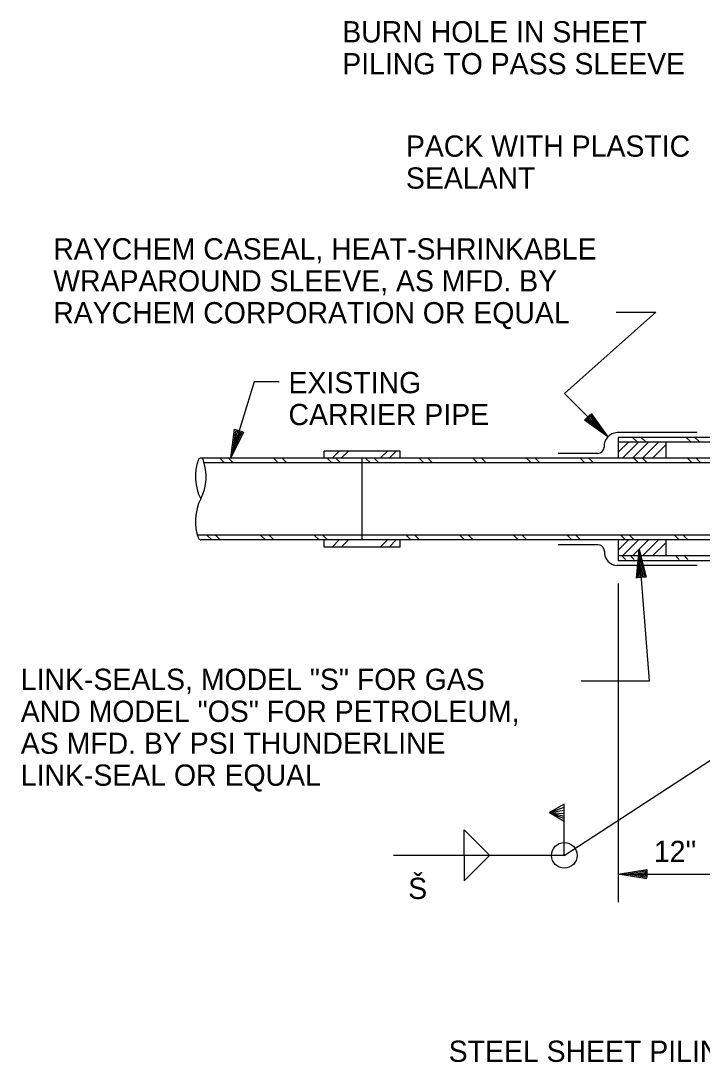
# Model space of a CAD drawing. Extents: x 22422.9 to 22498.9, y 22369.6 to 22415.
# Drawn here: x 22422.88 to 22428.87, y 22387.54 to 22396.69 of the extents above; entities that cross this region are included whole.
import ezdxf

# ---------------------------------------------------------------- set-up
doc = ezdxf.new("R2010")
doc.units = 0
for name, color, linetype in [('Level 1', 7, 'Continuous'), ('Level 10', 7, 'Continuous'), ('Level 2', 7, 'Continuous'), ('Level 4', 7, 'Continuous'), ('Level 7', 7, 'Continuous'), ('Level 8', 7, 'Continuous')]:
    doc.layers.add(name, color=color, linetype=linetype)

msp = doc.modelspace()

# ---------------------------------------------------------------- linework, layer by layer
at = {"layer": 'Level 1'}
for p, q in [((22431.1304, 22393.029), (22428.1304, 22393.029)), ((22431.1304, 22392.9873), (22428.1304, 22392.9873)), ((22428.1304, 22392.8989), (22428.2188, 22392.9873)), ((22428.1665, 22392.8467), (22428.3072, 22392.9873)), ((22428.2549, 22392.8467), (22428.3955, 22392.9873)), ((22428.3433, 22392.8467), (22428.4839, 22392.9873)), ((22428.4317, 22392.8467), (22428.5471, 22392.962)), ((22424.6447, 22392.9163), (22424.6447, 22392.9163)), ((22428.1304, 22392.0396), (22428.2188, 22392.1279)), ((22428.1665, 22391.9873), (22428.3072, 22392.1279)), ((22428.2549, 22391.9873), (22428.3955, 22392.1279)), ((22428.3433, 22391.9873), (22428.4839, 22392.1279)), ((22428.4317, 22391.9873), (22428.5471, 22392.1027)), ((22431.1304, 22391.9873), (22428.1304, 22391.9873)), ((22431.1304, 22391.9456), (22428.1304, 22391.9456)), ((22428.3613, 22391.9018), (22428.3613, 22391.9018)), ((22428.1304, 22391.7449), (22428.1304, 22388.946)), ((22428.1304, 22389.1938), (22429.1282, 22389.1938))]:
    msp.add_line(p, q, dxfattribs=at)
for centre, radius, start, end in [((22424.8524, 22392.683), 0.4356, 159.80644, 206.60705), ((22424.4636, 22392.826), 0.0213, 20.19356, 159.80644), ((22424.0748, 22392.683), 0.4356, 333.39295, 20.19356), ((22424.8524, 22392.2928), 0.4356, 153.39295, 200.19188), ((22424.4636, 22392.1498), 0.0213, 200.31546, 270)]:
    msp.add_arc(centre, radius, start, end, dxfattribs=at)
at = {"layer": 'Level 10'}
for p, q in [((22427.6563, 22389.3585), (22430.6304, 22391.2998)), ((22427.6563, 22389.8085), (22427.5261, 22389.7335)), ((22427.5261, 22389.7335), (22427.6563, 22389.7803)), ((22427.5261, 22389.7335), (22427.6563, 22389.7548)), ((22427.5261, 22389.7335), (22427.656, 22389.6585)), ((22427.5261, 22389.7335), (22427.6491, 22389.727)), ((22427.5261, 22389.7335), (22427.6536, 22389.7038)), ((22427.5261, 22389.7335), (22427.6563, 22389.6828)), ((22427.6563, 22389.3585), (22427.6563, 22389.8085)), ((22426.7776, 22389.5812), (22427.0011, 22389.3577)), ((22426.7776, 22389.3562), (22426.7776, 22389.5812)), ((22427.6563, 22389.3585), (22426.1558, 22389.3585)), ((22426.7776, 22389.3608), (22426.7776, 22389.1358)), ((22426.7776, 22389.1358), (22427.0011, 22389.3593))]:
    msp.add_line(p, q, dxfattribs=at)
msp.add_circle((22427.6563, 22389.3584), 0.1125, dxfattribs=at)
at = {"layer": 'Level 2'}
for p, q in [((22428.4615, 22394.1298), (22427.6575, 22393.4143)), ((22428.1107, 22394.1298), (22428.4615, 22394.1298)), ((22427.6575, 22393.4143), (22428.0385, 22393.0331)), ((22428.1304, 22393.029), (22428.1304, 22392.8467)), ((22428.5471, 22392.9873), (22428.5471, 22392.8467)), ((22431.1304, 22392.8467), (22424.4637, 22392.8467)), ((22425.5471, 22392.8467), (22425.5471, 22392.9092)), ((22426.2137, 22392.9092), (22425.5471, 22392.9092)), ((22425.8804, 22392.1279), (22425.8804, 22392.8467)), ((22426.2137, 22392.8467), (22426.2137, 22392.9092)), ((22431.1304, 22392.805), (22424.493, 22392.805)), ((22431.1304, 22392.1696), (22424.4346, 22392.1696)), ((22431.1304, 22392.1279), (22424.4649, 22392.1279)), ((22425.5471, 22392.0654), (22425.5471, 22392.1279)), ((22426.2137, 22392.0654), (22426.2137, 22392.1279)), ((22428.1304, 22392.1279), (22428.1304, 22391.9456)), ((22428.5471, 22392.1279), (22428.5471, 22391.9873)), ((22426.2137, 22392.0654), (22425.5471, 22392.0654))]:
    msp.add_line(p, q, dxfattribs=at)
for points in [[(22425.1514, 22393.518), (22424.9324, 22393.518), (22424.7269, 22392.8493)], [(22427.8914, 22393.2387), (22428.0385, 22393.0331), (22427.833, 22393.1803), (22427.8829, 22393.2302), (22427.9894, 22393.0822), (22427.8499, 22393.1822), (22427.882, 22393.2142), (22427.9423, 22393.1293), (22427.8669, 22393.184), (22427.8801, 22393.1972), (22427.8933, 22393.1784)], [(22424.8397, 22393.0755), (22424.7269, 22392.8493), (22424.7607, 22393.0998), (22424.8282, 22393.0791), (22424.7473, 22392.9156), (22424.7703, 22393.0857), (22424.8136, 22393.0724), (22424.7669, 22392.9793), (22424.7799, 22393.0716), (22424.7977, 22393.0661), (22424.7872, 22393.0456)], [(22427.8051, 22390.8923), (22428.4046, 22390.8923), (22428.3129, 22392.0452)], [(22428.2914, 22391.7934), (22428.3129, 22392.0452), (22428.3738, 22391.8), (22428.3034, 22391.7944), (22428.3184, 22391.9761), (22428.3597, 22391.8095), (22428.3145, 22391.8059), (22428.3236, 22391.9097), (22428.3456, 22391.8191), (22428.327, 22391.8176), (22428.3291, 22391.8406)], [(22428.3797, 22389.1525), (22428.1304, 22389.1938), (22428.3797, 22389.2352), (22428.3797, 22389.1645), (22428.1997, 22389.1938), (22428.3691, 22389.2218), (22428.3691, 22389.1765), (22428.2664, 22389.1938), (22428.3584, 22389.2085), (22428.3584, 22389.1898), (22428.3357, 22389.1938)]]:
    msp.add_lwpolyline(points, dxfattribs=at)
at = {"layer": 'Level 7'}
for p, q in [((22428.8237, 22393.0706), (22428.12, 22393.0706)), ((22427.9499, 22392.8883), (22427.6027, 22392.8883)), ((22427.9499, 22392.0863), (22427.6027, 22392.0863)), ((22428.8237, 22391.904), (22428.12, 22391.904))]:
    msp.add_line(p, q, dxfattribs=at)
for centre, radius, start, end in [((22428.1261, 22392.9499), 0.1209, 92.90014, 182.90014), ((22427.9499, 22392.9438), 0.0555, 270, 0), ((22427.9499, 22392.0282), 0.0581, 0, 90), ((22428.1261, 22392.0221), 0.1183, 177.03602, 267.03602)]:
    msp.add_arc(centre, radius, start, end, dxfattribs=at)
at = {"layer": 'Level 8'}
for p, q in [((22427.9894, 22393.0822), (22427.9894, 22393.0822)), ((22428.0385, 22393.0331), (22428.0385, 22393.0331)), ((22424.7269, 22392.8493), (22424.7269, 22392.8493)), ((22424.7473, 22392.9156), (22424.7473, 22392.9156)), ((22428.3129, 22392.0452), (22428.3129, 22392.0452)), ((22428.3184, 22391.9761), (22428.3184, 22391.9761)), ((22428.1304, 22389.1938), (22428.1304, 22389.1938)), ((22428.1997, 22389.1938), (22428.1997, 22389.1938))]:
    msp.add_line(p, q, dxfattribs=at)
for points in [[(22428.2927, 22392.9925), (22428.2563, 22393.029)], [(22428.3682, 22392.9925), (22428.3317, 22393.029)], [(22428.7641, 22392.9925), (22428.7277, 22393.029)], [(22428.8396, 22392.9925), (22428.8031, 22393.029)], [(22424.6727, 22392.805), (22424.631, 22392.8467)], [(22424.7481, 22392.805), (22424.7064, 22392.8467)], [(22425.1441, 22392.805), (22425.1024, 22392.8467)], [(22425.2195, 22392.805), (22425.1778, 22392.8467)], [(22425.6155, 22392.805), (22425.5738, 22392.8467)], [(22425.6804, 22392.9092), (22425.6179, 22392.8467)], [(22425.6909, 22392.805), (22425.6493, 22392.8467)], [(22425.7601, 22392.9092), (22425.6976, 22392.8467)], [(22425.9531, 22392.805), (22425.9114, 22392.8467)], [(22426.0268, 22392.805), (22425.9851, 22392.8467)], [(22426.1023, 22392.9092), (22426.0398, 22392.8467)], [(22426.1799, 22392.9092), (22426.1174, 22392.8467)], [(22426.4227, 22392.805), (22426.3811, 22392.8467)], [(22426.4982, 22392.805), (22426.4565, 22392.8467)], [(22426.8941, 22392.805), (22426.8525, 22392.8467)], [(22426.9696, 22392.805), (22426.9279, 22392.8467)], [(22427.3655, 22392.805), (22427.3239, 22392.8467)], [(22427.441, 22392.805), (22427.3993, 22392.8467)], [(22427.837, 22392.805), (22427.7953, 22392.8467)], [(22427.9124, 22392.805), (22427.8707, 22392.8467)], [(22428.3084, 22392.805), (22428.2667, 22392.8467)], [(22428.3838, 22392.805), (22428.3421, 22392.8467)], [(22428.7798, 22392.805), (22428.7381, 22392.8467)], [(22428.8552, 22392.805), (22428.8135, 22392.8467)], [(22424.5597, 22392.1279), (22424.518, 22392.1696)], [(22424.6351, 22392.1279), (22424.5935, 22392.1696)], [(22425.0311, 22392.1279), (22424.9894, 22392.1696)], [(22425.1065, 22392.1279), (22425.0649, 22392.1696)], [(22425.5025, 22392.1279), (22425.4609, 22392.1696)], [(22425.5779, 22392.1279), (22425.5363, 22392.1696)], [(22425.6804, 22392.1279), (22425.6179, 22392.0654)], [(22425.7601, 22392.1279), (22425.6976, 22392.0654)], [(22426.1023, 22392.1279), (22426.0398, 22392.0654)], [(22426.1799, 22392.1279), (22426.1174, 22392.0654)], [(22426.3086, 22392.1279), (22426.2669, 22392.1696)], [(22426.384, 22392.1279), (22426.3423, 22392.1696)], [(22426.78, 22392.1279), (22426.7383, 22392.1696)], [(22426.8554, 22392.1279), (22426.8137, 22392.1696)], [(22427.2514, 22392.1279), (22427.2097, 22392.1696)], [(22427.3268, 22392.1279), (22427.2851, 22392.1696)], [(22427.7228, 22392.1279), (22427.6811, 22392.1696)], [(22427.7982, 22392.1279), (22427.7565, 22392.1696)], [(22428.1942, 22392.1279), (22428.1525, 22392.1696)], [(22428.2696, 22392.1279), (22428.228, 22392.1696)], [(22428.6656, 22392.1279), (22428.6239, 22392.1696)], [(22428.741, 22392.1279), (22428.6994, 22392.1696)], [(22428.1942, 22391.9561), (22428.1682, 22391.9821)], [(22428.2696, 22391.9561), (22428.2436, 22391.9821)], [(22428.6656, 22391.9561), (22428.6396, 22391.9821)], [(22428.741, 22391.9561), (22428.715, 22391.9821)]]:
    msp.add_lwpolyline(points, dxfattribs=at)

# ---------------------------------------------------------------- texts
at = {"layer": 'Level 4'}
for s, height, p in [('BURN HOLE IN SHEET', 0.186667, (22425.7062, 22396.4975)), ('PILING TO PASS SLEEVE', 0.186667, (22425.7062, 22396.2171)), ('PACK WITH PLASTIC', 0.186667, (22426.2651, 22395.4935)), ('SEALANT', 0.18667, (22426.2651, 22395.2131)), ('RAYCHEM CASEAL, HEAT-SHRINKABLE', 0.186667, (22423.168, 22394.591)), ('WRAPAROUND SLEEVE, AS MFD. BY', 0.186667, (22423.168, 22394.3105)), ('RAYCHEM CORPORATION OR EQUAL', 0.186667, (22423.168, 22394.0301)), ('EXISTING', 0.18667, (22425.2342, 22393.4168)), ('CARRIER PIPE', 0.186667, (22425.2342, 22393.1364)), ('LINK-SEALS, MODEL "S" FOR GAS', 0.186667, (22422.8828, 22390.8107)), ('AND MODEL "OS" FOR PETROLEUM,', 0.186667, (22422.8828, 22390.5303)), ('AS MFD. BY PSI THUNDERLINE', 0.186667, (22422.8828, 22390.2499)), ('LINK-SEAL OR EQUAL', 0.186667, (22422.8828, 22389.9695)), ("12''", 0.18667, (22428.4426, 22389.2994)), ('Š', 0.1867, (22426.2855, 22388.9751)), ('STEEL SHEET PILING', 0.186667, (22426.6406, 22387.5448))]:
    msp.add_text(s, height=height, dxfattribs=at).set_placement(p)

doc.saveas('drawing.dxf')
